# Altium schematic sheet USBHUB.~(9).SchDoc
size A
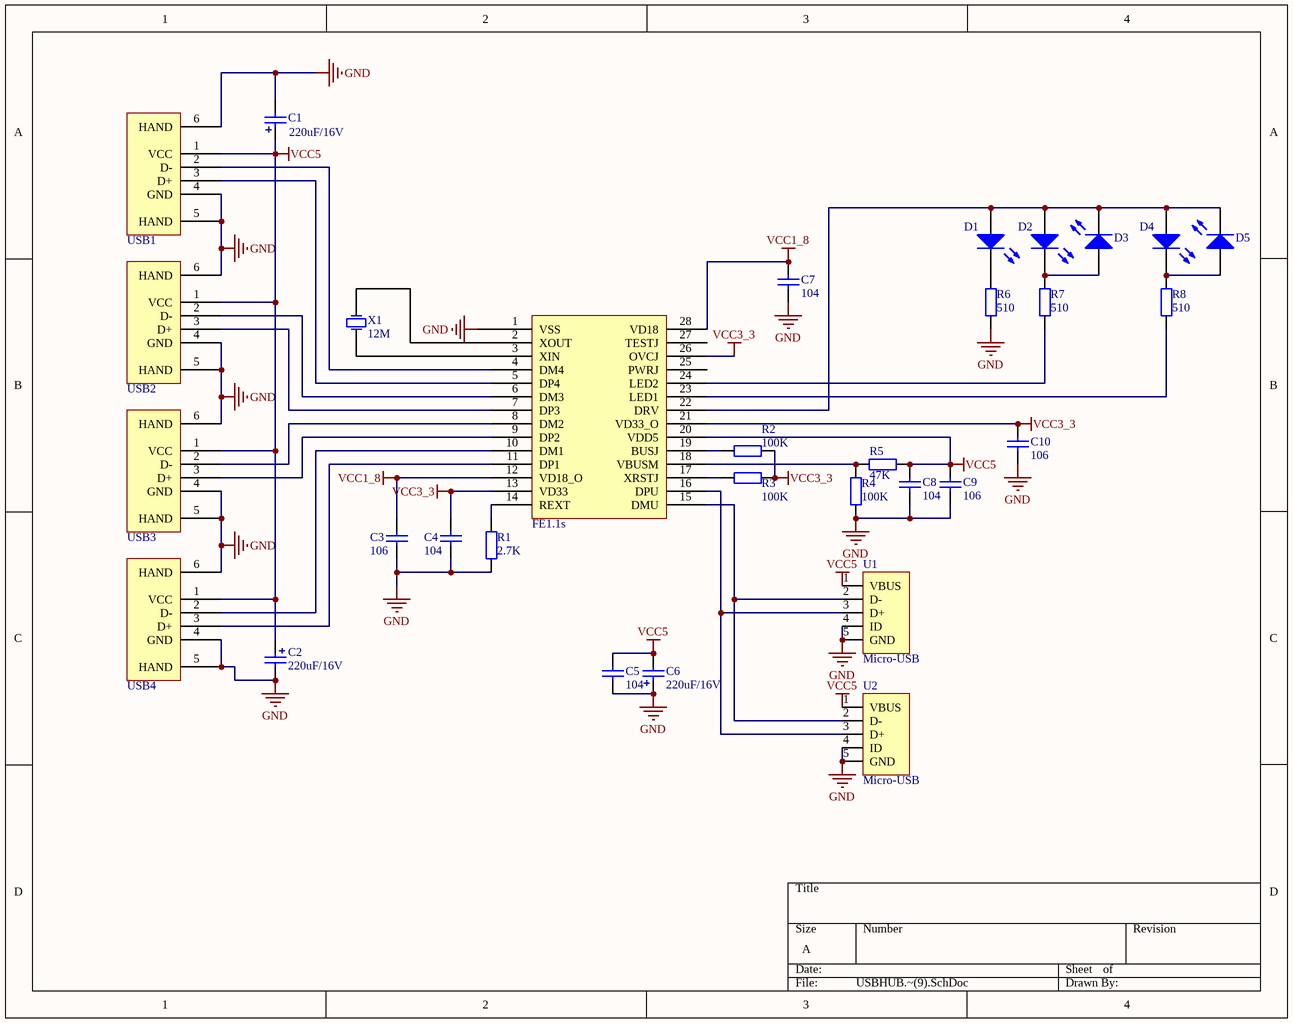
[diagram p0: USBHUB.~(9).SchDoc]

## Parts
C1  value 220uF/16V  [cap_220uF/16V]  (hidden comment: Cap_Pol)
C2  value 220uF/16V  [cap_220uF/16V]  (hidden comment: Cap_Pol)
C3  value 106  [2012[0805]-C]  (hidden comment: Cap1)
C4  value 104  [2012[0805]-C]  (hidden comment: Cap1)
C5  value 104  [2012[0805]-C]  (hidden comment: Cap1)
C6  value 220uF/16V  [cap_220uF/16V]  (hidden comment: Cap_Pol)
C7  value 104  [2012[0805]-C]  (hidden comment: Cap1)
C8  value 104  [2012[0805]-C]  (hidden comment: Cap1)
C9  value 106  [2012[0805]-C]  (hidden comment: Cap1)
C10  value 106  [2012[0805]-C]  (hidden comment: Cap1)
D1  LED  [LED1]  (value not drawn)
D2  LED  [LED1]  (value not drawn)
D3  LED  [LED1]  (value not drawn)
D4  LED  [LED1]  (value not drawn)
D5  LED  [LED1]  (value not drawn)
FE1.1s  FE1.1s  [SSOP-28]  (value not drawn)
R1  value 2.7K  [2012[0805]-R]  (hidden comment: Res1)
R2  value 100K  [2012[0805]-R]  (hidden comment: Res1)
R3  value 100K  [2012[0805]-R]  (hidden comment: Res1)
R4  value 100K  [2012[0805]-R]  (hidden comment: Res1)
R5  value 47K  [2012[0805]-R]  (hidden comment: Res1)
R6  value 510  [2012[0805]-R]  (hidden comment: Res1)
R7  value 510  [2012[0805]-R]  (hidden comment: Res1)
R8  value 510  [2012[0805]-R]  (hidden comment: Res1)
U1  Micro-USB  [Micro-USB]
U2  Micro-USB  [Micro-USB]
USB1  USB  [USB2.5-2V4A]  (value not drawn)
USB2  USB  [USB2.5-2V4A]  (value not drawn)
USB3  USB  [USB2.5-2V4A]  (value not drawn)
USB4  USB  [USB2.5-2V4A]  (value not drawn)
X1  12M  [XTAL]

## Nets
GND: C1.2 C2.2 C3.1 C4.1 C5.1 C6.1 C7.2 C8.1 C9.1 C10.1 R1.1 R4.1 R6.1 U1.4(ID) U1.5(GND) U2.4(ID) U2.5(GND) USB1.4(GND) USB1.5(HAND) USB1.6(HAND) USB2.4(GND) USB2.5(HAND) USB2.6(HAND) USB3.4(GND) USB3.5(HAND) USB3.6(HAND) USB4.4(GND) USB4.5(HAND) USB4.6(HAND)
VCC1_8: C3.2 C7.1 FE1.1s.12(VD18_O) FE1.1s.28(VD18)
VCC3_3: C4.2 C10.2 FE1.1s.13(VD33) FE1.1s.21(VD33_O) FE1.1s.26(OVCJ) R2.2 R3.2
VCC5: C1.1 C2.1 C5.2 C6.2 C8.2 C9.2 FE1.1s.20(VDD5) R5.2 U1.1(VBUS) U2.1(VBUS) USB1.1(VCC) USB2.1(VCC) USB3.1(VCC) USB4.1(VCC)
NetD1_1: D1.1(A) D2.1(A) D3.2(K) D4.1(A) D5.2(K) FE1.1s.22(DRV)
NetD1_2: D1.2(K) R6.2
NetD2_2: D2.2(K) D3.1(A) R7.2
NetD4_2: D4.2(K) D5.1(A) R8.2
NetFE1.1s_4: FE1.1s.4(DM4) USB1.2(D-)
NetFE1.1s_5: FE1.1s.5(DP4) USB1.3(D+)
NetFE1.1s_6: FE1.1s.6(DM3) USB2.2(D-)
NetFE1.1s_7: FE1.1s.7(DP3) USB2.3(D+)
NetFE1.1s_8: FE1.1s.8(DM2) USB3.2(D-)
NetFE1.1s_9: FE1.1s.9(DP2) USB3.3(D+)
NetFE1.1s_10: FE1.1s.10(DM1) USB4.2(D-)
NetFE1.1s_11: FE1.1s.11(DP1) USB4.3(D+)
NetFE1.1s_14: FE1.1s.14(REXT) R1.2
NetFE1.1s_15: FE1.1s.15(DMU) U1.2(D-) U2.2(D-)
NetFE1.1s_16: FE1.1s.16(DPU) U1.3(D+) U2.3(D+)
NetFE1.1s_17: FE1.1s.17(XRSTJ) R3.1
NetFE1.1s_18: FE1.1s.18(VBUSM) R4.2 R5.1
NetFE1.1s_19: FE1.1s.19(BUSJ) R2.1
NetFE1.1s_23: FE1.1s.23(LED1) R8.1
NetFE1.1s_24: FE1.1s.24(LED2) R7.1

Not connected (* = marked no-connect by the designer): FE1.1s 1(VSS) 2(XOUT) 3(XIN) 25(PWRJ) 27(TESTJ); X1 1(OSC1) 2(OSC2)

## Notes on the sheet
- Labels drawn without touching a wire or pin: GND

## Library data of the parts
C1 C2 C6 = Cap_Pol: Capacitor
C3-C5 C7-C10 = Cap1: Capacitor
D1-D5 = LED1: Typical INFRARED GaAs LED
R1-R8 = Res1: Resistor
X1 = XTAL_1: Crystal Oscillator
